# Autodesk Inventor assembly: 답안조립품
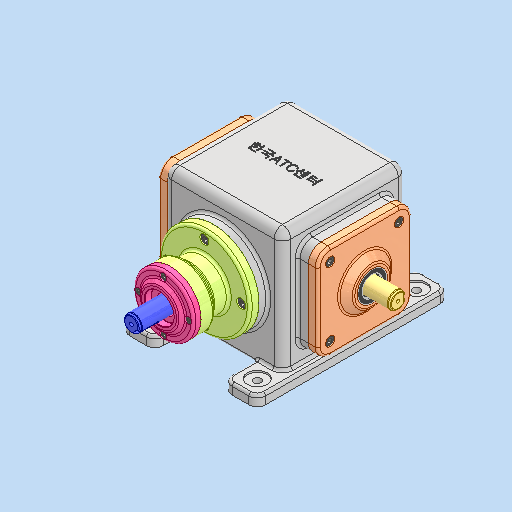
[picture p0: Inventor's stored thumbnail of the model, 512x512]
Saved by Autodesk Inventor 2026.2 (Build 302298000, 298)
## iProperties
Created: 2026-01
Part Number: 답안조립품
Document SubType Name: Assembly
Designer: PC2-07
Author: PC2-07
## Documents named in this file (16)
- C:\Users\PC2-07\Desktop\760103V1005\답안조립품.iam
- C:\Users\PC2-07\Desktop\760103V1005\본체.ipt
- C:\Users\PC2-07\Desktop\760103V1005\종동축\종동축\종동축.ipt
- C:\Users\PC2-07\Desktop\760103V1005\테이퍼 롤러 베어링 30204K\테이퍼 롤러 베어링 30204K\테이퍼 롤러 베어링 30204K.ipt
- C:\Users\PC2-07\Desktop\760103V1005\평행 키 6x6x18\평행 키 6x6x18\평행 키 6x6x18.ipt
- C:\Users\PC2-07\Desktop\760103V1005\베벨 기어(종동)\베벨 기어(종동)\베벨 기어(종동).ipt
- C:\Users\PC2-07\Desktop\760103V1005\칼라\칼라\칼라.ipt
- C:\Users\PC2-07\Desktop\760103V1005\측면 커버\측면 커버\측면 커버.ipt
- C:\Users\PC2-07\Desktop\760103V1005\오일 실 20 35 8\오일 실 20 35 8\오일 실 20 35 8.ipt
- C:\Users\PC2-07\Desktop\760103V1005\베어링 하우징\베어링 하우징\베어링 하우징.ipt
- C:\Users\PC2-07\Desktop\760103V1005\하우징 커버\하우징 커버\하우징 커버.ipt
- C:\Users\PC2-07\Desktop\760103V1005\구동축\구동축\구동축.ipt
- C:\Users\PC2-07\Desktop\760103V1005\베벨 기어(구동)\베벨 기어(구동)\베벨 기어(구동).ipt
- C:\Users\PC2-07\Desktop\760103V1005\엔드캡\엔드캡\엔드캡.ipt
- C:\Users\PC2-07\Desktop\760103V1005\6각 구멍붙이 볼트 M6x12\6각 구멍붙이 볼트 M6x12\6각 구멍붙이 볼트 M6x12.ipt
- C:\Users\PC2-07\Desktop\760103V1005\6각 구멍붙이 볼트 M4x10\6각 구멍붙이 볼트 M4x10\6각 구멍붙이 볼트 M4x10.ipt
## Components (19 placed, 4 different names)
1. 하우징 커버:1
2. 구동축:1
3. 6각 구멍붙이 볼트 M6x12:1
4. 6각 구멍붙이 볼트 M6x12:2
5. 6각 구멍붙이 볼트 M6x12:3
6. 6각 구멍붙이 볼트 M6x12:4
7. 6각 구멍붙이 볼트 M6x12:5
8. 6각 구멍붙이 볼트 M6x12:6
9. 6각 구멍붙이 볼트 M6x12:7
10. 6각 구멍붙이 볼트 M6x12:8
11. 6각 구멍붙이 볼트 M6x12:9
12. 6각 구멍붙이 볼트 M6x12:10
13. 6각 구멍붙이 볼트 M6x12:11
14. 6각 구멍붙이 볼트 M6x12:12
15. 6각 구멍붙이 볼트 M6x12:13
16. 6각 구멍붙이 볼트 M4x10:1
17. 6각 구멍붙이 볼트 M4x10:2
18. 6각 구멍붙이 볼트 M4x10:3
19. 6각 구멍붙이 볼트 M4x10:4
